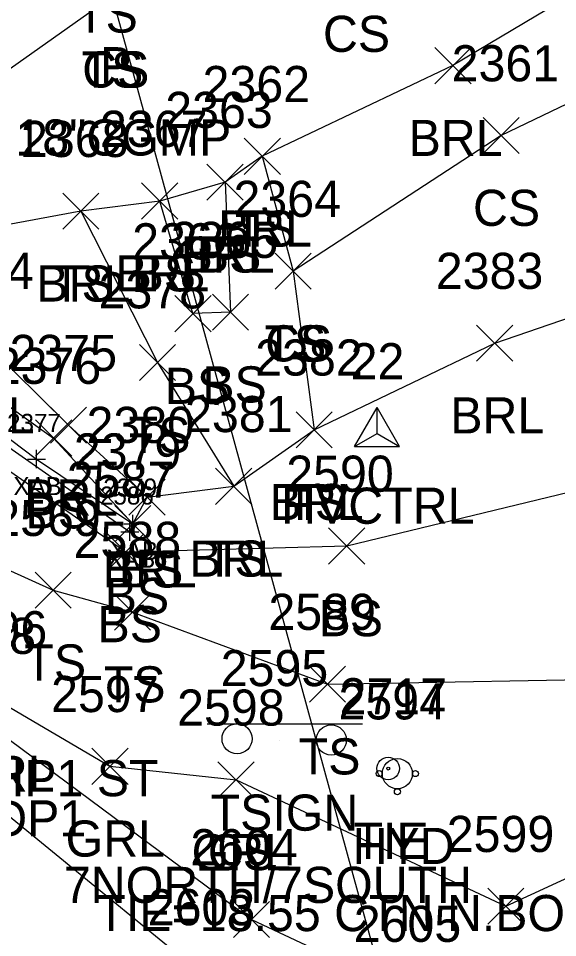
# Model space of a CAD drawing. Extents: x 1504228 to 1506103, y 437717 to 440106.
# Drawn here: x 1505301.1 to 1505331, y 438136.5 to 438187.4 of the extents above; entities that cross this region are included whole.
import ezdxf

# ---------------------------------------------------------------- set-up
doc = ezdxf.new("R2010")
doc.units = 0
for name, color, linetype in [('B_A', 7, 'Continuous'), ('B_I', 7, 'Continuous'), ('B_TIC', 7, 'Continuous'), ('BSUBM', 7, 'Continuous'), ('C_A', 7, 'Continuous'), ('C_C', 7, 'Continuous'), ('C_I', 7, 'Continuous'), ('CBP', 7, 'Continuous'), ('CPSM', 7, 'Continuous'), ('D_A', 7, 'Continuous'), ('D_C', 7, 'Continuous'), ('DCP', 7, 'Continuous'), ('L_A', 7, 'Continuous'), ('L_I', 7, 'Continuous'), ('L_TIC', 7, 'Continuous'), ('LABL', 7, 'Continuous'), ('LELB', 7, 'Continuous'), ('P_I', 7, 'Continuous'), ('P_TIC', 7, 'Continuous'), ('PET', 7, 'Continuous'), ('PSP', 7, 'Continuous'), ('R_A', 7, 'Continuous'), ('R_I', 7, 'Continuous'), ('R_TIC', 7, 'Continuous'), ('RGR', 7, 'Continuous'), ('S_A', 7, 'Continuous'), ('S_C', 7, 'Continuous'), ('S_I', 7, 'Continuous'), ('SSGN', 7, 'Continuous'), ('U_A', 7, 'Continuous'), ('U_I', 7, 'Continuous'), ('UWFH', 7, 'Continuous')]:
    doc.layers.add(name, color=color, linetype=linetype)

msp = doc.modelspace()

# ---------------------------------------------------------------- linework, layer by layer
at = {"layer": 'B_TIC'}
for p, q in [((1505302.14, 438162.984), (1505302.215, 438162.984)), ((1505307.472, 438159.403), (1505307.547, 438159.403)), ((1505307.31, 438158.962), (1505307.385, 438158.962)), ((1505307.31, 438158.962), (1505307.385, 438158.962))]:
    msp.add_line(p, q, dxfattribs=at)
for points in [[(1505302.136, 438162.484), (1505302.136, 438163.484)], [(1505301.636, 438162.984), (1505302.636, 438162.984)], [(1505307.468, 438158.903), (1505307.468, 438159.903)], [(1505306.968, 438159.403), (1505307.968, 438159.403)], [(1505307.306, 438158.462), (1505307.306, 438159.462)], [(1505307.306, 438158.462), (1505307.306, 438159.462)], [(1505306.806, 438158.962), (1505307.806, 438158.962)], [(1505306.806, 438158.962), (1505307.806, 438158.962)]]:
    msp.add_lwpolyline(points, dxfattribs=at)
at = {"layer": 'BSUBM'}
for points in [[(1505214.761, 438127.389), (1505213.65, 438134.809), (1505212.657, 438139.975), (1505231.134, 438147.944), (1505243.637, 438153.412), (1505246.753, 438154.837), (1505263.932, 438162.477), (1505271.425, 438165.886), (1505277.465, 438168.561), (1505287.974, 438173.167), (1505291.052, 438171.05), (1505297.268, 438166.649), (1505302.136, 438162.984), (1505307.468, 438159.403), (1505307.306, 438158.962)], [(1505282.757, 438168.549), (1505282.349, 438168.267), (1505281.249, 438169.437), (1505281.958, 438169.702), (1505282.224, 438169.899), (1505283.084, 438168.636), (1505285.392, 438170.489), (1505285.041, 438171.11), (1505285.421, 438171.342), (1505288.006, 438172.324), (1505295.913, 438166.903), (1505307.306, 438158.962)]]:
    msp.add_lwpolyline(points, dxfattribs=at)
at = {"layer": 'CBP'}
for radius in [0.625, 0.0833]:
    msp.add_circle((1505321.597, 438145.852), radius, dxfattribs=at)
at = {"layer": 'CPSM'}
for p, q in [((1505319.731, 438163.678), (1505320.981, 438165.843)), ((1505322.231, 438163.678), (1505320.981, 438165.843)), ((1505320.981, 438164.399), (1505320.981, 438165.843)), ((1505319.731, 438163.678), (1505320.981, 438164.399)), ((1505320.981, 438164.399), (1505320.981, 438164.399)), ((1505320.981, 438164.399), (1505322.231, 438163.678)), ((1505319.731, 438163.678), (1505322.231, 438163.678))]:
    msp.add_line(p, q, dxfattribs=at)
at = {"layer": 'DCP'}
msp.add_lwpolyline([(1505306.265, 438188.781), (1505322.088, 438131.045)], dxfattribs=at)
at = {"layer": 'L_TIC'}
for points in [[(1505324.182, 438183.758), (1505326.182, 438185.758)], [(1505326.182, 438183.758), (1505324.182, 438185.758)], [(1505326.848, 438179.889), (1505328.848, 438181.889)], [(1505328.848, 438179.889), (1505326.848, 438181.889)], [(1505313.631, 438178.74), (1505315.631, 438180.74)], [(1505315.631, 438178.74), (1505313.631, 438180.74)], [(1505313.631, 438178.74), (1505315.631, 438180.74)], [(1505315.631, 438178.74), (1505313.631, 438180.74)], [(1505311.566, 438177.307), (1505313.566, 438179.307)], [(1505313.566, 438177.307), (1505311.566, 438179.307)], [(1505311.566, 438177.307), (1505313.566, 438179.307)], [(1505313.566, 438177.307), (1505311.566, 438179.307)], [(1505307.953, 438176.263), (1505309.953, 438178.263)], [(1505309.953, 438176.263), (1505307.953, 438178.263)], [(1505307.953, 438176.263), (1505309.953, 438178.263)], [(1505309.953, 438176.263), (1505307.953, 438178.263)], [(1505303.583, 438175.7), (1505305.583, 438177.7)], [(1505305.583, 438175.7), (1505303.583, 438177.7)], [(1505303.583, 438175.7), (1505305.583, 438177.7)], [(1505305.583, 438175.7), (1505303.583, 438177.7)], [(1505315.341, 438172.385), (1505317.341, 438174.385)], [(1505317.341, 438172.385), (1505315.341, 438174.385)], [(1505315.341, 438172.385), (1505317.341, 438174.385)], [(1505317.341, 438172.385), (1505315.341, 438174.385)], [(1505309.792, 438170.033), (1505311.792, 438172.033)], [(1505311.792, 438170.033), (1505309.792, 438172.033)], [(1505311.868, 438170.115), (1505313.868, 438172.115)], [(1505313.868, 438170.115), (1505311.868, 438172.115)], [(1505326.49, 438168.4), (1505328.49, 438170.4)], [(1505328.49, 438168.4), (1505326.49, 438170.4)], [(1505307.829, 438167.322), (1505309.829, 438169.322)], [(1505309.829, 438167.322), (1505307.829, 438169.322)], [(1505302.904, 438163.856), (1505304.904, 438165.856)], [(1505304.904, 438163.856), (1505302.904, 438165.856)], [(1505316.495, 438163.603), (1505318.495, 438165.603)], [(1505318.495, 438163.603), (1505316.495, 438165.603)], [(1505316.495, 438163.603), (1505318.495, 438165.603)], [(1505318.495, 438163.603), (1505316.495, 438165.603)], [(1505302.084, 438163.144), (1505304.084, 438165.144)], [(1505304.084, 438163.144), (1505302.084, 438165.144)], [(1505312.047, 438160.473), (1505314.047, 438162.473)], [(1505314.047, 438160.473), (1505312.047, 438162.473)], [(1505312.047, 438160.473), (1505314.047, 438162.473)], [(1505314.047, 438160.473), (1505312.047, 438162.473)], [(1505307.252, 438159.874), (1505309.252, 438161.874)], [(1505309.252, 438159.874), (1505307.252, 438161.874)], [(1505307.252, 438159.874), (1505309.252, 438161.874)], [(1505309.252, 438159.874), (1505307.252, 438161.874)], [(1505306.468, 438158.403), (1505308.468, 438160.403)], [(1505308.468, 438158.403), (1505306.468, 438160.403)], [(1505306.071, 438156.841), (1505308.071, 438158.841)], [(1505308.071, 438156.841), (1505306.071, 438158.841)], [(1505318.301, 438157.173), (1505320.301, 438159.173)], [(1505320.301, 438157.173), (1505318.301, 438159.173)], [(1505302.056, 438154.723), (1505304.056, 438156.723)], [(1505304.056, 438154.723), (1505302.056, 438156.723)], [(1505306.447, 438153.511), (1505308.447, 438155.511)], [(1505308.447, 438153.511), (1505306.447, 438155.511)], [(1505317.234, 438149.525), (1505319.234, 438151.525)], [(1505319.234, 438149.525), (1505317.234, 438151.525)], [(1505312.175, 438144.226), (1505314.175, 438146.226)], [(1505314.175, 438144.226), (1505312.175, 438146.226)], [(1505327.105, 438137.232), (1505329.105, 438139.232)], [(1505329.105, 438137.232), (1505327.105, 438139.232)]]:
    msp.add_lwpolyline(points, dxfattribs=at)
at = {"layer": 'LABL'}
msp.add_lwpolyline([(1505412.94, 438279.434), (1505408.751, 438263.902), (1505393.358, 438239.3), (1505379.992, 438219.583), (1505364.652, 438204.996), (1505342.27, 438194.948), (1505325.182, 438184.758), (1505314.631, 438179.74), (1505312.566, 438178.307), (1505308.953, 438177.263), (1505304.583, 438176.7), (1505296.615, 438175.22), (1505299.292, 438169.398), (1505303.904, 438164.856), (1505308.252, 438160.874), (1505313.047, 438161.473), (1505317.495, 438164.603), (1505327.49, 438169.4), (1505342.058, 438174.403)], dxfattribs=at)
at = {"layer": 'LELB'}
for points in [[(1505408.751, 438263.902), (1505398.015, 438236.03), (1505385.067, 438213.947), (1505364.652, 438204.996), (1505348.803, 438190.971), (1505327.848, 438180.889), (1505316.341, 438173.385)], [(1505283.082, 438168.26), (1505293.755, 438159.929), (1505303.056, 438155.723), (1505307.447, 438154.511), (1505318.234, 438150.525), (1505336.416, 438150.851), (1505352.472, 438164.545), (1505373.298, 438174.049), (1505384.454, 438185.345), (1505390.057, 438193.61)], [(1505280.724, 438166.502), (1505281.778, 438166.802), (1505283.082, 438168.26), (1505285.843, 438169.435), (1505295.117, 438166.148), (1505307.071, 438157.841), (1505319.301, 438158.173), (1505335.681, 438162.149), (1505348.978, 438167.874), (1505368.148, 438177.626), (1505382.147, 438186.406), (1505384.268, 438190.42)], [(1505215.631, 438142.954), (1505216.782, 438152.684), (1505223.21, 438155.651), (1505231.417, 438162.88), (1505240.87, 438166.496), (1505250.977, 438169.557), (1505260.591, 438172.084), (1505271.035, 438170.915), (1505277.265, 438170.598), (1505281.518, 438175.58), (1505287.828, 438178.641), (1505292.056, 438179.708), (1505296.753, 438181.832), (1505306.221, 438188.545)], [(1505314.631, 438179.74), (1505316.341, 438173.385), (1505317.495, 438164.603)], [(1505312.566, 438178.307), (1505312.868, 438171.115), (1505310.792, 438171.033), (1505308.953, 438177.263)], [(1505304.583, 438176.7), (1505308.829, 438168.322), (1505313.047, 438161.473)], [(1505296.615, 438175.22), (1505292.362, 438172.302), (1505297.993, 438167.769), (1505303.084, 438164.144), (1505307.468, 438159.403), (1505308.252, 438160.874)], [(1505313.175, 438145.226), (1505328.105, 438138.232), (1505341.684, 438144.494), (1505357.679, 438159.862), (1505373.298, 438174.049)]]:
    msp.add_lwpolyline(points, dxfattribs=at)
at = {"layer": 'P_TIC'}
for points in [[(1505313.034, 438136.497), (1505315.034, 438138.497)], [(1505315.034, 438136.497), (1505313.034, 438138.497)]]:
    msp.add_lwpolyline(points, dxfattribs=at)
at = {"layer": 'PET'}
msp.add_lwpolyline([(1505219.541, 438139.332), (1505229.478, 438143.453), (1505236.137, 438147.016), (1505243.065, 438149.521), (1505252.019, 438153.342), (1505263.781, 438158.664), (1505277.038, 438164.677), (1505295.889, 438147.093), (1505311.676, 438134.175), (1505338.301, 438109.134), (1505363.246, 438092.977), (1505381.83, 438081.07), (1505419.293, 438061.963), (1505441.952, 438049.929), (1505474.016, 438032.73)], dxfattribs=at)
at = {"layer": 'PSP'}
msp.add_lwpolyline([(1505298.089, 438149.32), (1505314.034, 438137.497), (1505323.075, 438133.257), (1505335.82, 438133.23)], dxfattribs=at)
at = {"layer": 'R_TIC'}
for points in [[(1505305.202, 438144.976), (1505307.202, 438146.976)], [(1505307.202, 438144.976), (1505305.202, 438146.976)], [(1505312.175, 438144.226), (1505314.175, 438146.226)], [(1505314.175, 438144.226), (1505312.175, 438146.226)]]:
    msp.add_lwpolyline(points, dxfattribs=at)
at = {"layer": 'RGR'}
msp.add_lwpolyline([(1505281.778, 438166.802), (1505300.096, 438149.564), (1505306.202, 438145.976), (1505313.175, 438145.226)], dxfattribs=at)
at = {"layer": 'SSGN'}
for p, q in [((1505311.572, 438148.334), (1505320.169, 438148.334)), ((1505315.594, 438147.43), (1505315.594, 438147.43))]:
    msp.add_line(p, q, dxfattribs=at)
for centre in [(1505313.233, 438147.5), (1505318.448, 438147.43)]:
    msp.add_circle(centre, 0.833, dxfattribs=at)
at = {"layer": 'UWFH'}
msp.add_line((1505322.104, 438145.57), (1505322.104, 438145.57), dxfattribs=at)
for centre, radius in [((1505322.104, 438145.57), 0.833), ((1505321.104, 438145.57), 0.167), ((1505323.104, 438145.57), 0.167), ((1505322.104, 438144.57), 0.167)]:
    msp.add_circle(centre, radius, dxfattribs=at)

# ---------------------------------------------------------------- texts
at = {"layer": 'B_A'}
for s, p in [('XAB', (1505300.857, 438160.984)), ('XAB', (1505306.189, 438157.403)), ('XAT', (1505306.011, 438156.962)), ('XAB', (1505306.027, 438156.962))]:
    msp.add_text(s, height=1, dxfattribs=at).set_placement(p)
at = {"layer": 'B_I'}
for s, p in [('2377', (1505300.506, 438164.484)), ('2379', (1505305.834, 438160.903)), ('2586', (1505305.649, 438160.462)), ('2586', (1505305.649, 438160.462))]:
    msp.add_text(s, height=1, dxfattribs=at).set_placement(p)
at = {"layer": 'C_A'}
for s, p in [('HVCTRL', (1505315.674, 438159.399)), ('TIE', (1505319.675, 438140.852))]:
    msp.add_text(s, height=2, dxfattribs=at).set_placement(p)
at = {"layer": 'C_C'}
msp.add_text('TIE=18.55 CTN N.BOLT', height=2, dxfattribs=at).set_placement((1505305.447, 438136.852))
at = {"layer": 'C_I'}
for s, p in [('22', (1505319.517, 438167.399)), ('2717', (1505318.904, 438148.852))]:
    msp.add_text(s, height=2, dxfattribs=at).set_placement(p)
at = {"layer": 'D_A'}
msp.add_text('P', height=2, dxfattribs=at).set_placement((1505305.643, 438183.781))
at = {"layer": 'D_C'}
msp.add_text('18"CGMP', height=2, dxfattribs=at).set_placement((1505300.966, 438179.781))
at = {"layer": 'L_A'}
for s, p in [('TS', (1505304.324, 438186.586)), ('CS', (1505317.987, 438185.519)), ('TS', (1505304.631, 438183.545)), ('CS', (1505304.662, 438183.545)), ('BRL', (1505322.726, 438179.758)), ('CS', (1505326.289, 438175.889)), ('BRL', (1505312.175, 438174.74)), ('TS', (1505313.041, 438174.74)), ('BRL', (1505310.109, 438173.307)), ('BS', (1505311.007, 438173.307)), ('BRL', (1505306.496, 438172.263)), ('BS', (1505307.394, 438172.263)), ('BRL', (1505302.126, 438171.7)), ('TS', (1505302.993, 438171.7)), ('TS', (1505314.751, 438168.385)), ('CS', (1505314.782, 438168.385)), ('BS', (1505309.233, 438166.033)), ('BS', (1505311.309, 438166.115)), ('BRL', (1505296.836, 438164.398)), ('BRL', (1505325.033, 438164.4)), ('TS', (1505307.239, 438163.322)), ('BRL', (1505301.447, 438159.856)), ('BRL', (1505315.039, 438159.603)), ('TS', (1505315.905, 438159.603)), ('BS', (1505301.525, 438159.144)), ('BRL', (1505310.59, 438156.473)), ('TS', (1505311.456, 438156.473)), ('BRL', (1505305.795, 438155.874)), ('BS', (1505306.692, 438155.874)), ('BS', (1505305.909, 438154.403)), ('BS', (1505317.742, 438153.173)), ('BS', (1505305.512, 438152.841)), ('TS', (1505301.465, 438150.723)), ('TS', (1505305.857, 438149.511)), ('TS', (1505316.644, 438145.525)), ('CS', (1505311.615, 438140.226))]:
    msp.add_text(s, height=2, dxfattribs=at).set_placement(p)
at = {"layer": 'L_I'}
for s, p in [('2361', (1505325.108, 438183.889)), ('2362', (1505311.324, 438182.74)), ('2362', (1505311.324, 438182.74)), ('2363', (1505309.259, 438181.307)), ('2363', (1505309.259, 438181.307)), ('2367', (1505305.646, 438180.263)), ('2367', (1505305.646, 438180.263)), ('2368', (1505301.276, 438179.7)), ('2368', (1505301.276, 438179.7)), ('2364', (1505313.034, 438176.385)), ('2364', (1505313.034, 438176.385)), ('2366', (1505307.43, 438174.033)), ('2365', (1505309.561, 438174.115)), ('2374', (1505296.032, 438172.398)), ('2383', (1505324.23, 438172.4)), ('2378', (1505305.57, 438171.322)), ('2375', (1505300.644, 438167.856)), ('2382', (1505314.235, 438167.603)), ('2382', (1505314.235, 438167.603)), ('2376', (1505299.769, 438167.144)), ('2381', (1505310.354, 438164.473)), ('2381', (1505310.354, 438164.473)), ('2380', (1505304.905, 438163.874)), ('2380', (1505304.905, 438163.874)), ('2379', (1505304.2, 438162.403)), ('2587', (1505303.811, 438160.841)), ('2590', (1505315.954, 438161.173)), ('2569', (1505299.741, 438158.723)), ('2588', (1505304.187, 438157.511)), ('2589', (1505314.967, 438153.525)), ('2598', (1505309.915, 438148.226)), ('2599', (1505324.837, 438141.232))]:
    msp.add_text(s, height=2, dxfattribs=at).set_placement(p)
at = {"layer": 'P_I'}
for s, p in [('2604', (1505310.648, 438140.497)), ('2603', (1505308.29, 438137.175)), ('2603', (1505308.29, 438137.175)), ('2605', (1505319.689, 438136.257))]:
    msp.add_text(s, height=2, dxfattribs=at).set_placement(p)
at = {"layer": 'R_A'}
for s, p in [('GRL', (1505297.639, 438144.564)), ('SWP1 SHP1 ST', (1505289.42, 438144.32)), ('SWP1 RDP1', (1505289.433, 438142.093)), ('GRL', (1505303.746, 438140.976)), ('GRL', (1505310.718, 438140.226))]:
    msp.add_text(s, height=2, dxfattribs=at).set_placement(p)
at = {"layer": 'R_I'}
for s, p in [('2596', (1505296.781, 438152.564)), ('2597', (1505302.943, 438148.976)), ('2598', (1505309.915, 438148.226))]:
    msp.add_text(s, height=2, dxfattribs=at).set_placement(p)
at = {"layer": 'S_A'}
msp.add_text('TSIGN', height=2, dxfattribs=at).set_placement((1505311.77, 438142.412))
at = {"layer": 'S_C'}
for s, p in [('US7 BR108', (1505287.989, 438152.198)), ('7NORTH/7SOUTH', (1505303.652, 438138.412))]:
    msp.add_text(s, height=2, dxfattribs=at).set_placement(p)
at = {"layer": 'S_I'}
msp.add_text('2595', height=2, dxfattribs=at).set_placement((1505312.329, 438150.412))
at = {"layer": 'U_A'}
msp.add_text('HYD', height=2, dxfattribs=at).set_placement((1505319.624, 438140.57))
at = {"layer": 'U_I'}
msp.add_text('2594', height=2, dxfattribs=at).set_placement((1505318.844, 438148.57))

doc.saveas('drawing.dxf')
